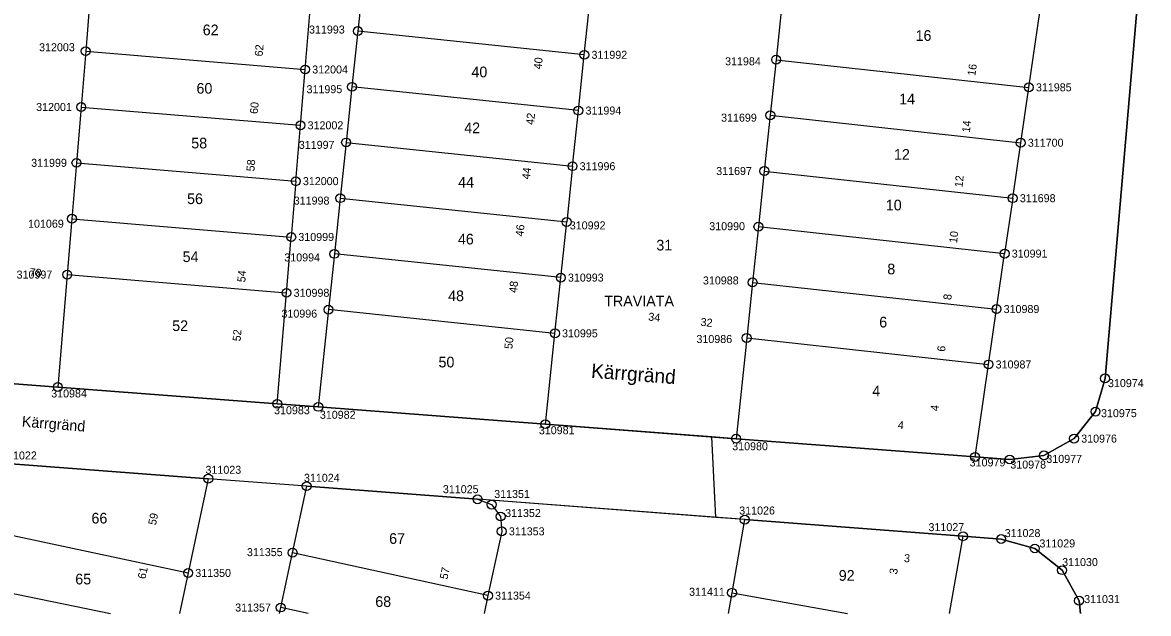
# Model space of a CAD drawing. Extents: x 141995 to 152570, y 6580184 to 6586000.
# Drawn here: x 142245.6 to 142372.2, y 6585000 to 6585066.5 of the extents above; entities that cross this region are included whole.
import ezdxf

# ---------------------------------------------------------------- set-up
doc = ezdxf.new("R2010")
doc.units = 0
for name, color, linetype in [('Level 10', 7, 'Continuous'), ('Level 42', 7, 'Continuous'), ('Level 43', 7, 'Continuous'), ('Level 5', 7, 'Continuous'), ('Level 51', 7, 'Continuous'), ('Level 53', 7, 'Continuous'), ('Level 54', 7, 'Continuous'), ('Level 55', 7, 'Continuous'), ('Level 58', 7, 'Continuous'), ('Level 59', 7, 'Continuous'), ('Level 6', 7, 'Continuous'), ('Level 7', 7, 'Continuous')]:
    doc.layers.add(name, color=color, linetype=linetype)

msp = doc.modelspace()

# ---------------------------------------------------------------- linework, layer by layer
at = {"layer": 'Level 10'}
for centre in [(142283.35, 6585065.51), (142252.75, 6585063.25), (142308.81, 6585062.84), (142330.38, 6585062.29), (142277.42, 6585061.19), (142282.69, 6585059.24), (142358.79, 6585059.18), (142252.24, 6585056.97), (142308.15, 6585056.57), (142329.72, 6585056.04), (142276.9, 6585054.91), (142282.03, 6585052.98), (142357.88, 6585052.95), (142251.71, 6585050.69), (142307.49, 6585050.31), (142329.05, 6585049.77), (142276.37, 6585048.62), (142281.37, 6585046.71), (142356.98, 6585046.71), (142251.2, 6585044.4), (142306.83, 6585044.04), (142328.39, 6585043.51), (142275.86, 6585042.34), (142280.71, 6585040.45), (142356.07, 6585040.48), (142250.67, 6585038.12), (142306.17, 6585037.78), (142327.73, 6585037.24), (142275.33, 6585036.07), (142280.05, 6585034.18), (142355.16, 6585034.24), (142305.51, 6585031.51), (142327.07, 6585030.99), (142354.26, 6585028.01), (142367.36, 6585026.44), (142249.62, 6585025.47), (142274.29, 6585023.58), (142278.9, 6585023.24), (142366.29, 6585022.71), (142304.43, 6585021.29), (142325.88, 6585019.66), (142363.88, 6585019.67), (142352.75, 6585017.61), (142360.49, 6585017.78), (142356.64, 6585017.32), (142266.53, 6585015.16), (142277.6, 6585014.32), (142296.81, 6585012.85), (142298.39, 6585012.25), (142299.4, 6585010.91), (142326.85, 6585010.56), (142299.53, 6585009.24), (142351.39, 6585008.69), (142355.68, 6585008.37), (142276.01, 6585006.84), (142359.46, 6585007.31), (142362.53, 6585004.87), (142264.27, 6585004.56), (142325.42, 6585002.33), (142297.98, 6585002.01), (142364.44, 6585001.44), (142274.68, 6585000.67)]:
    msp.add_circle(centre, 0.5, dxfattribs=at)
at = {"layer": 'Level 5'}
for points in [[(142376.84, 6585136.75), (142367.36, 6585026.44)], [(142249.62, 6585025.47), (142228.18, 6585027.1)], [(142367.36, 6585026.44), (142366.29, 6585022.71)], [(142274.29, 6585023.58), (142249.62, 6585025.47)], [(142278.9, 6585023.24), (142274.29, 6585023.58)], [(142304.43, 6585021.29), (142278.9, 6585023.24)], [(142366.29, 6585022.71), (142363.88, 6585019.67)], [(142323.14, 6585019.87), (142304.43, 6585021.29)], [(142325.88, 6585019.66), (142323.14, 6585019.87)], [(142352.75, 6585017.61), (142325.88, 6585019.66)], [(142363.88, 6585019.67), (142360.49, 6585017.78)], [(142243.89, 6585016.87), (142266.53, 6585015.16)], [(142356.64, 6585017.32), (142352.75, 6585017.61)], [(142360.49, 6585017.78), (142356.64, 6585017.32)], [(142277.6, 6585014.32), (142266.53, 6585015.16)], [(142277.6, 6585014.32), (142296.81, 6585012.85)], [(142323.61, 6585010.81), (142296.81, 6585012.85)], [(142326.85, 6585010.56), (142323.61, 6585010.81)], [(142326.85, 6585010.56), (142351.39, 6585008.69)], [(142351.39, 6585008.69), (142355.68, 6585008.37)], [(142355.68, 6585008.37), (142359.46, 6585007.31)], [(142359.46, 6585007.31), (142362.53, 6585004.87)], [(142362.53, 6585004.87), (142364.44, 6585001.44)], [(142364.44, 6585001.44), (142364.6, 6585000)]]:
    msp.add_lwpolyline(points, dxfattribs=at)
at = {"layer": 'Level 6'}
for points in [[(142228.18, 6585027.1), (142249.62, 6585025.47), (142274.29, 6585023.58), (142278.9, 6585023.24), (142304.43, 6585021.29), (142325.88, 6585019.66), (142352.75, 6585017.61), (142356.64, 6585017.32), (142360.49, 6585017.78), (142363.88, 6585019.67), (142366.29, 6585022.71), (142367.36, 6585026.44), (142376.84, 6585136.75), (142377.99, 6585153.73), (142378.15, 6585158.76), (142377.61, 6585162.31), (142375.87, 6585165.44), (142373.13, 6585167.75), (142369.76, 6585168.94), (142367.8, 6585169.26), (142344.13, 6585173.11), (142322.83, 6585176.58), (142298, 6585180.62)], [(142364.6, 6585000), (142364.44, 6585001.44), (142362.53, 6585004.87), (142359.46, 6585007.31), (142355.68, 6585008.37), (142351.39, 6585008.69), (142326.85, 6585010.56), (142296.81, 6585012.85), (142277.6, 6585014.32), (142266.53, 6585015.16), (142243.89, 6585016.87)]]:
    msp.add_lwpolyline(points, dxfattribs=at)
at = {"layer": 'Level 7'}
for points in [[(142284.01, 6585071.78), (142283.35, 6585065.51)], [(142331.3, 6585071.1), (142330.38, 6585062.29)], [(142253.27, 6585069.55), (142252.75, 6585063.25)], [(142308.81, 6585062.84), (142309.48, 6585069.1)], [(142277.42, 6585061.19), (142277.95, 6585067.47)], [(142358.79, 6585059.18), (142360.02, 6585067.65)], [(142283.35, 6585065.51), (142282.69, 6585059.24)], [(142308.81, 6585062.84), (142283.35, 6585065.51)], [(142252.75, 6585063.25), (142252.24, 6585056.97)], [(142252.75, 6585063.25), (142277.42, 6585061.19)], [(142308.15, 6585056.57), (142308.81, 6585062.84)], [(142330.38, 6585062.29), (142329.72, 6585056.04)], [(142330.38, 6585062.29), (142358.79, 6585059.18)], [(142276.9, 6585054.91), (142277.42, 6585061.19)], [(142282.69, 6585059.24), (142282.03, 6585052.98)], [(142308.15, 6585056.57), (142282.69, 6585059.24)], [(142357.88, 6585052.95), (142358.79, 6585059.18)], [(142252.24, 6585056.97), (142251.71, 6585050.69)], [(142252.24, 6585056.97), (142276.9, 6585054.91)], [(142307.49, 6585050.31), (142308.15, 6585056.57)], [(142329.72, 6585056.04), (142329.05, 6585049.77)], [(142329.72, 6585056.04), (142357.88, 6585052.95)], [(142276.37, 6585048.62), (142276.9, 6585054.91)], [(142282.03, 6585052.98), (142281.37, 6585046.71)], [(142282.03, 6585052.98), (142307.49, 6585050.31)], [(142356.98, 6585046.71), (142357.88, 6585052.95)], [(142251.71, 6585050.69), (142251.2, 6585044.4)], [(142251.71, 6585050.69), (142276.37, 6585048.62)], [(142307.49, 6585050.31), (142306.83, 6585044.04)], [(142329.05, 6585049.77), (142328.39, 6585043.51)], [(142329.05, 6585049.77), (142356.98, 6585046.71)], [(142276.37, 6585048.62), (142275.86, 6585042.34)], [(142281.37, 6585046.71), (142280.71, 6585040.45)], [(142281.37, 6585046.71), (142306.83, 6585044.04)], [(142356.98, 6585046.71), (142356.07, 6585040.48)], [(142251.2, 6585044.4), (142250.67, 6585038.12)], [(142251.2, 6585044.4), (142275.86, 6585042.34)], [(142306.17, 6585037.78), (142306.83, 6585044.04)], [(142328.39, 6585043.51), (142327.73, 6585037.24)], [(142328.39, 6585043.51), (142356.07, 6585040.48)], [(142275.33, 6585036.07), (142275.86, 6585042.34)], [(142280.71, 6585040.45), (142280.05, 6585034.18)], [(142306.17, 6585037.78), (142280.71, 6585040.45)], [(142355.16, 6585034.24), (142356.07, 6585040.48)], [(142250.67, 6585038.12), (142249.62, 6585025.47)], [(142250.67, 6585038.12), (142275.33, 6585036.07)], [(142305.51, 6585031.51), (142306.17, 6585037.78)], [(142327.73, 6585037.24), (142327.07, 6585030.99)], [(142327.73, 6585037.24), (142355.16, 6585034.24)], [(142274.29, 6585023.58), (142275.33, 6585036.07)], [(142280.05, 6585034.18), (142278.9, 6585023.24)], [(142305.51, 6585031.51), (142280.05, 6585034.18)], [(142354.26, 6585028.01), (142355.16, 6585034.24)], [(142304.43, 6585021.29), (142305.51, 6585031.51)], [(142327.07, 6585030.99), (142325.88, 6585019.66)], [(142327.07, 6585030.99), (142354.26, 6585028.01)], [(142352.75, 6585017.61), (142354.26, 6585028.01)], [(142323.61, 6585010.81), (142323.14, 6585019.87)], [(142266.53, 6585015.16), (142264.27, 6585004.56)], [(142276.01, 6585006.84), (142277.6, 6585014.32)], [(142296.81, 6585012.85), (142298.39, 6585012.25)], [(142298.39, 6585012.25), (142299.4, 6585010.91)], [(142299.4, 6585010.91), (142299.53, 6585009.24)], [(142325.42, 6585002.33), (142326.85, 6585010.56)], [(142242.27, 6585009.26), (142264.27, 6585004.56)], [(142299.53, 6585009.24), (142297.98, 6585002.01)], [(142349.88, 6585000), (142351.39, 6585008.69)], [(142274.68, 6585000.67), (142276.01, 6585006.84)], [(142297.98, 6585002.01), (142276.01, 6585006.84)], [(142264.27, 6585004.56), (142263.29, 6585000)], [(142240.92, 6585003.01), (142255.55, 6585000)], [(142297.98, 6585002.01), (142297.55, 6585000)], [(142325.01, 6585000), (142325.42, 6585002.33)], [(142325.42, 6585002.33), (142338.4, 6585000)], [(142274.54, 6585000), (142274.68, 6585000.67)], [(142277.75, 6585000), (142274.68, 6585000.67)]]:
    msp.add_lwpolyline(points, dxfattribs=at)

# ---------------------------------------------------------------- texts
at = {"layer": 'Level 42'}
msp.add_text('Kärrgränd', height=1.2, rotation=355.4611, dxfattribs=at).set_placement((142245.54, 6585021.02))
at = {"layer": 'Level 43'}
msp.add_text('Kärrgränd', height=1.6, rotation=355.6401, dxfattribs=at).set_placement((142309.54, 6585026.52))
at = {"layer": 'Level 51'}
for s, p in [('62', (142265.91, 6585065.04)), ('16', (142346.06, 6585064.41)), ('40', (142296.12, 6585060.31)), ('60', (142265.21, 6585058.47)), ('14', (142344.21, 6585057.27)), ('42', (142295.31, 6585054.02)), ('58', (142264.62, 6585052.31)), ('12', (142343.63, 6585051.04)), ('44', (142294.63, 6585047.91)), ('56', (142264.15, 6585046.05)), ('10', (142342.71, 6585045.34)), ('46', (142294.6, 6585041.51)), ('54', (142263.65, 6585039.53)), ('8', (142342.88, 6585038.15)), ('48', (142293.5, 6585035.13)), ('6', (142341.97, 6585032.17)), ('52', (142262.48, 6585031.77)), ('50', (142292.42, 6585027.68)), ('4', (142341.19, 6585024.43)), ('66', (142253.4, 6585010.12)), ('67', (142286.87, 6585007.83)), ('65', (142251.58, 6585003.27)), ('92', (142337.42, 6585003.68)), ('68', (142285.31, 6585000.74))]:
    msp.add_text(s, height=1.2, rotation=0.0522, dxfattribs=at).set_placement(p)
at = {"layer": 'Level 53'}
for s, p in [('311993', (142277.86, 6585065.23)), ('312003', (142247.51, 6585063.24)), ('311992', (142309.62, 6585062.39)), ('311984', (142324.64, 6585061.66)), ('312004', (142278.22, 6585060.74)), ('311995', (142277.58, 6585058.52)), ('311985', (142359.59, 6585058.73)), ('312001', (142247.18, 6585056.52)), ('311994', (142308.95, 6585056.12)), ('311699', (142324.19, 6585055.32)), ('312002', (142277.7, 6585054.46)), ('311700', (142358.68, 6585052.5)), ('311997', (142276.71, 6585052.26)), ('311999', (142246.62, 6585050.24)), ('311996', (142308.29, 6585049.86)), ('311697', (142323.64, 6585049.32)), ('312000', (142277.17, 6585048.18)), ('311698', (142357.78, 6585046.26)), ('311998', (142276.14, 6585045.99)), ('101069', (142246.27, 6585043.39)), ('310992', (142307.18, 6585043.2)), ('310990', (142322.86, 6585043.11)), ('310999', (142276.66, 6585041.9)), ('310991', (142356.87, 6585040.03)), ('310994', (142275.08, 6585039.6)), ('310997', (142244.98, 6585037.67)), ('310993', (142306.97, 6585037.33)), ('310988', (142322.15, 6585037.01)), ('310998', (142276.13, 6585035.62)), ('310989', (142355.96, 6585033.79)), ('310996', (142274.76, 6585033.28)), ('310995', (142306.31, 6585031.06)), ('310986', (142321.42, 6585030.42)), ('310987', (142355.06, 6585027.56)), ('310974', (142367.69, 6585025.46)), ('310984', (142248.87, 6585024.3)), ('310983', (142273.93, 6585022.41)), ('310982', (142279.08, 6585021.9)), ('310975', (142366.91, 6585022.08)), ('310981', (142303.7, 6585020.16)), ('310980', (142325.44, 6585018.36)), ('310976', (142364.68, 6585019.22)), ('311022', (142243.24, 6585017.32)), ('310979', (142352.14, 6585016.54)), ('310978', (142356.71, 6585016.3)), ('310977', (142360.76, 6585016.94)), ('311023', (142266.22, 6585015.71)), ('311024', (142277.29, 6585014.81)), ('311025', (142292.91, 6585013.53)), ('311351', (142298.68, 6585012.99)), ('311352', (142299.91, 6585010.85)), ('311026', (142326.23, 6585011.13)), ('311353', (142300.33, 6585008.79)), ('311027', (142347.51, 6585009.26)), ('311028', (142356.08, 6585008.59)), ('311029', (142359.98, 6585007.43)), ('311355', (142270.88, 6585006.45)), ('311030', (142362.54, 6585005.33)), ('311350', (142265.07, 6585004.11)), ('311411', (142320.59, 6585001.99)), ('311354', (142298.78, 6585001.56)), ('311031', (142365.01, 6585001.17)), ('311357', (142269.56, 6585000.22))]:
    msp.add_text(s, height=0.9, rotation=0.0522, dxfattribs=at).set_placement(p)
at = {"layer": 'Level 54'}
for s, rotation, p in [('62', 85.1838, (142272.64, 6585062.63)), ('40', 83.9708, (142304, 6585061.17)), ('16', 81.7399, (142352.77, 6585060.43)), ('60', 85.1838, (142272.1, 6585056.16)), ('42', 83.9808, (142303.14, 6585054.92)), ('14', 83.8948, (142352.16, 6585054.07)), ('58', 85.1838, (142271.71, 6585049.7)), ('44', 83.9718, (142302.68, 6585048.8)), ('12', 83.8958, (142351.33, 6585047.9)), ('46', 83.9738, (142301.96, 6585042.38)), ('10', 83.9128, (142350.72, 6585041.63)), ('78', 355.3371, (142246.41, 6585037.95)), ('54', 85.2178, (142270.69, 6585037.23)), ('48', 83.9708, (142301.23, 6585036.02)), ('8', 83.8958, (142350.06, 6585035.23)), ('34', 353.802, (142315.97, 6585032.96)), ('32', 353.802, (142321.84, 6585032.37)), ('52', 85.2448, (142270.16, 6585030.59)), ('50', 83.9738, (142300.71, 6585029.71)), ('6', 83.8948, (142349.37, 6585029.41)), ('4', 83.8958, (142348.62, 6585022.74)), ('59', 77.984, (142260.64, 6585009.88)), ('61', 77.973, (142259.46, 6585003.82)), ('57', 77.991, (142293.42, 6585003.78)), ('3', 79.7539, (142343.97, 6585004.35))]:
    msp.add_text(s, height=0.9, rotation=rotation, dxfattribs=at).set_placement(p)
at = {"layer": 'Level 55'}
for s, rotation, p in [('4', 355.6471, (142344.04, 6585020.78)), ('3', 355.6481, (142344.73, 6585005.79))]:
    msp.add_text(s, height=0.9, rotation=rotation, dxfattribs=at).set_placement(p)
at = {"layer": 'Level 58'}
msp.add_text('TRAVIATA', height=1.2, rotation=0.0522, dxfattribs=at).set_placement((142311.05, 6585034.54))
at = {"layer": 'Level 59'}
msp.add_text('31', height=1.2, rotation=0.0522, dxfattribs=at).set_placement((142316.91, 6585040.83))

doc.saveas('drawing.dxf')
